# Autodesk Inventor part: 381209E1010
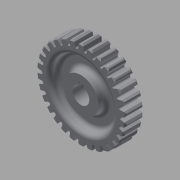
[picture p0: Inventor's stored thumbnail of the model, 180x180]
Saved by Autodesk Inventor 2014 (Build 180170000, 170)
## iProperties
Created: 2018-12
Part Number: 381209E1010
Material: Generic
Document SubType Name: Modeling
Designer: kh
Density: 1 g/cm^3
Appearance: Default
Mass: 28.8455 g
Surface Area: 115.678 cm^2
Volume: 28.8455 cm^3
Author: kh
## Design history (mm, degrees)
sketch "Sketch1"
  geometry: L1 (-32, 0)-(32, 0); L2 (0, 0.813)-(0, 38.391); C1 r 30 at (0, 0); A1 r 32 centre (0, 0) between (-32, 0) and (32, 0); A2 r 27.5 centre (0, 0) between (-2, 27.427) and (2, 27.427); A3 r 32 centre (0, 0) between (1.5, 31.965) and (-1.5, 31.965); A4 r 37.907 centre (-35.861, 25.552) between (2, 27.427) and (1.5, 31.965); A5 r 37.907 centre (35.861, 25.552) between (-1.5, 31.965) and (-2, 27.427); 5 further points
  constraints: 12 point on circle, 6 centre point, 4 coincident, 4 end point, 3 symmetric about line, 2 midpoint, 1 horizontal, 1 perpendicular, 1 point on line, 4 other
  dimensions: "d5" = 2 radial gap between concentric circles of A1 C1; "d6" = 60 diameter of C1 (= 30 x d5); "d7" = 2.5 dimension on C1 (= 1.25 x d5); "d13" = 37.90697 radius of A4; "d14" = 32 radius of A3; "d15" = 3 distance of A3.start A3.end; "d16" = 4 distance of A2.end A2.start
extrude "Extrusion1" new body sketch "Sketch1" distance "d17" = 13; taper "d18" = 0 deg
chamfer "Chamfer1" distance "d22" = 1; stored, may be unused: second distance "d23" = 2, angle "d24" = 45 deg
fillet "Fillet1" dims "d25" = 1
chamfer "Chamfer2" distance "d29" = 1; stored, may be unused: second distance "d30" = 2, angle "d31" = 45 deg
sketch "Sketch2"
  geometry: L1 (28.275, 13)-(27.353, 13) reference; L2 (28.275, 13)-(30.956, 13) reference; L3 (30.956, 13)-(30.956, 13) reference; L4 (30.956, 13)-(28.275, 13) reference; L5 (27.353, 13)-(28.275, 13) reference; L6 (27.353, 13)-(27.346, 13) reference; L7 (28.063, 13)-(27.346, 13) reference; L8 (28.063, 13)-(30.624, 13) reference; L9 (29.934, 13)-(30.624, 13) reference; L10 (29.934, 13)-(27.252, 13) reference; L11 (26.164, 13)-(27.252, 13) reference; L12 (26.164, 13)-(26.144, 13) reference; L13 (26.623, 13)-(26.144, 13) reference; L14 (26.623, 13)-(28.954, 13) reference; L15 (27.604, 13)-(28.954, 13) reference; L16 (27.604, 13)-(25.038, 13) reference; L17 (23.832, 13)-(25.038, 13) reference; L18 (23.832, 13)-(23.8, 13) reference; L19 (24.021, 13)-(23.8, 13) reference; L20 (24.021, 13)-(26.019, 13) reference; L21 (24.068, 13)-(26.019, 13) reference; L22 (24.068, 13)-(21.73, 13) reference; L23 (20.458, 13)-(21.73, 13) reference; L24 (20.458, 13)-(20.415, 13) reference; L25 (20.368, 13)-(20.415, 13) reference; L26 (20.368, 13)-(21.946, 13) reference; L27 (19.48, 13)-(21.946, 13) reference; L28 (19.48, 13)-(17.472, 13) reference; L29 (16.19, 13)-(17.472, 13) reference; L30 (16.19, 13)-(16.138, 13) reference; L31 (15.825, 13)-(16.138, 13) reference; L32 (15.825, 13)-(16.915, 13) reference; L33 (14.041, 13)-(16.915, 13) reference; L34 (14.041, 13)-(12.45, 13) reference; L35 (11.215, 13)-(12.45, 13) reference; L36 (11.215, 13)-(11.156, 13) reference; L37 (10.591, 13)-(11.156, 13) reference; L38 (10.591, 13)-(11.144, 13) reference; L39 (7.988, 13)-(11.144, 13) reference; L40 (7.988, 13)-(6.885, 13) reference; L41 (5.749, 13)-(6.885, 13) reference; L42 (5.749, 13)-(5.686, 13) reference; L43 (4.893, 13)-(5.686, 13) reference; L44 (4.893, 13)-(4.886, 13) reference; L45 (1.586, 13)-(4.886, 13) reference; L46 (1.586, 13)-(1.018, 13) reference; L47 (0.032, 13)-(1.018, 13) reference; L48 (0.032, 13)-(-0.032, 13) reference; L49 (-1.018, 13)-(-0.032, 13) reference; L50 (-1.018, 13)-(-1.586, 13) reference; L51 (-4.886, 13)-(-1.586, 13) reference; L52 (-4.886, 13)-(-4.893, 13) reference; L53 (-5.686, 13)-(-4.893, 13) reference; L54 (-5.686, 13)-(-5.749, 13) reference; L55 (-6.885, 13)-(-5.749, 13) reference; L56 (-6.885, 13)-(-7.988, 13) reference; L57 (-11.144, 13)-(-7.988, 13) reference; L58 (-11.144, 13)-(-10.591, 13) reference; L59 (-11.156, 13)-(-10.591, 13) reference; L60 (-11.156, 13)-(-11.215, 13) reference; L61 (-12.45, 13)-(-11.215, 13) reference; L62 (-12.45, 13)-(-14.041, 13) reference; L63 (-16.915, 13)-(-14.041, 13) reference; L64 (-16.915, 13)-(-15.825, 13) reference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; 1 further point
  constraints: 10 end point, 3 perpendicular, 1 collinear, 1 horizontal, 1 parallel
  dimensions: "d35" = 7 distance between parallel lines of L337 L184; "d36" = 45 diameter of L366 L365; "d37" = 25 diameter of L183 L365
revolve "Revolution1" sketch "Sketch2" stored, may be unused: angle "d38" = 90 deg
fillet "Fillet2" dims "d39" = 3
sketch "Sketch3" dims "d40" = 12
  geometry: L1 (-2, 7.768)-(2, 7.768); L2 (2, 7.768)-(2, -0.032); L3 (2, -0.032)-(-2, -0.032); L4 (-2, -0.032)-(-2, 7.768); L5 (0, -6.032)-(0, 7.768); 2 further points
  constraints: 10 end point, 2 midpoint, 2 parallel, 1 coincident, 1 horizontal, 1 perpendicular, 1 point on line, 1 vertical, 1 vertical alignment, 2 other
  dimensions: "d41" = 13.8 dimension on L1; "d42" = 4 distance of L1.start L1.end
extrude "Extrusion2" cut sketch "Sketch3" stored distance "d43" = 13; taper "d44" = 0 deg
body "Solid1"
pattern_circular "Circular Pattern3" dims "d33" = 360 deg
node "Projected Loop1"
node "Projected Loop2"
other parameters: "d12" = 3
